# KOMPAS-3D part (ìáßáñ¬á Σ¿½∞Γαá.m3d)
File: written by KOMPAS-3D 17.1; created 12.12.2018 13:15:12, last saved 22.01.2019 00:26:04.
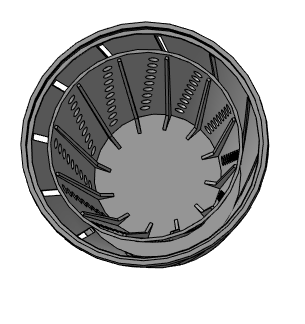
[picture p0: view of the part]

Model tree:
1. Тело насадки
2. Выдавить Тело насадки
     Угол 1 = 360
3. Угловой переход
4. Выдавливание перехода
     Расстояние 1 = 3
5. Вырез под замок
6. Вырезание паза
     Расстояние 1 = 4
7. Входной паз замка
8. Выдавливание паза
     Угол 1 = 360
9. Плоскость отверстия
     Расстояние = 24
10. Профиль отверстия
11. Выдавить Профиль отверстия
     Расстояние 1 = 15
12. Скругление:29
     Радиус = 2
13. Массив по концентрической сетке:1  (with: Выдавить Профиль отверстия, Скругление:29)  (12 pattern instances)
     Шаг 2 = 360
14. Опора фильтра
15. Выдавить Опора фильтра
     Угол 1 = 360
16. Скругление:31
     Радиус = 2
17. Смещенная плоскость:2
     Расстояние = 3
18. Эскиз:2
19. Ребро жесткости:4
     Толщина стенки 1 = 1; Толщина стенки 2 = 1
20. Массив по концентрической сетке:3  (with: Ребро жесткости:4, Смещенная плоскость:2, Выдавить Опора фильтра)  (12 pattern instances)
     Шаг 2 = 360
21. Профиль Перфорации
22. Элемент выдавливания:1
     Расстояние 2 = 25.4689; Смещение 2 = 1
23. Массив по концентрической сетке:4  (with: Элемент выдавливания:1)  (12 pattern instances)
     Шаг 2 = 360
